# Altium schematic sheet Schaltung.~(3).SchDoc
size A4
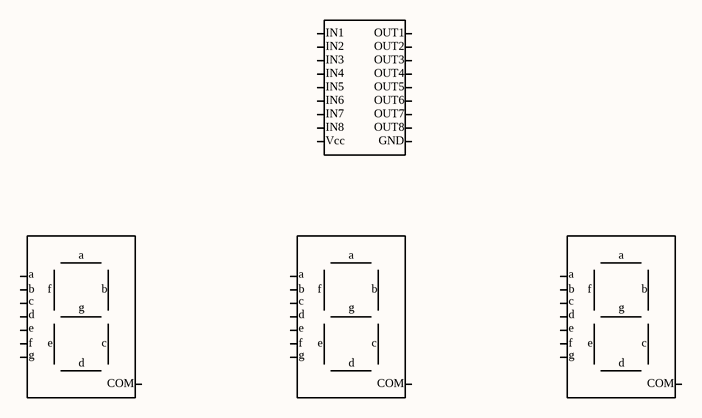
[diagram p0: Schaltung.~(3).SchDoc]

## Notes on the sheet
- IN1
- IN2
- IN3
- IN4
- OUT1
- OUT2
- OUT3
- OUT4
- IN5
- IN6
- IN7
- IN8
- Vcc
- OUT5
- OUT6
- OUT7
- OUT8
- GND
- a
- b
- f
- c
- d
- e
- g
- COM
